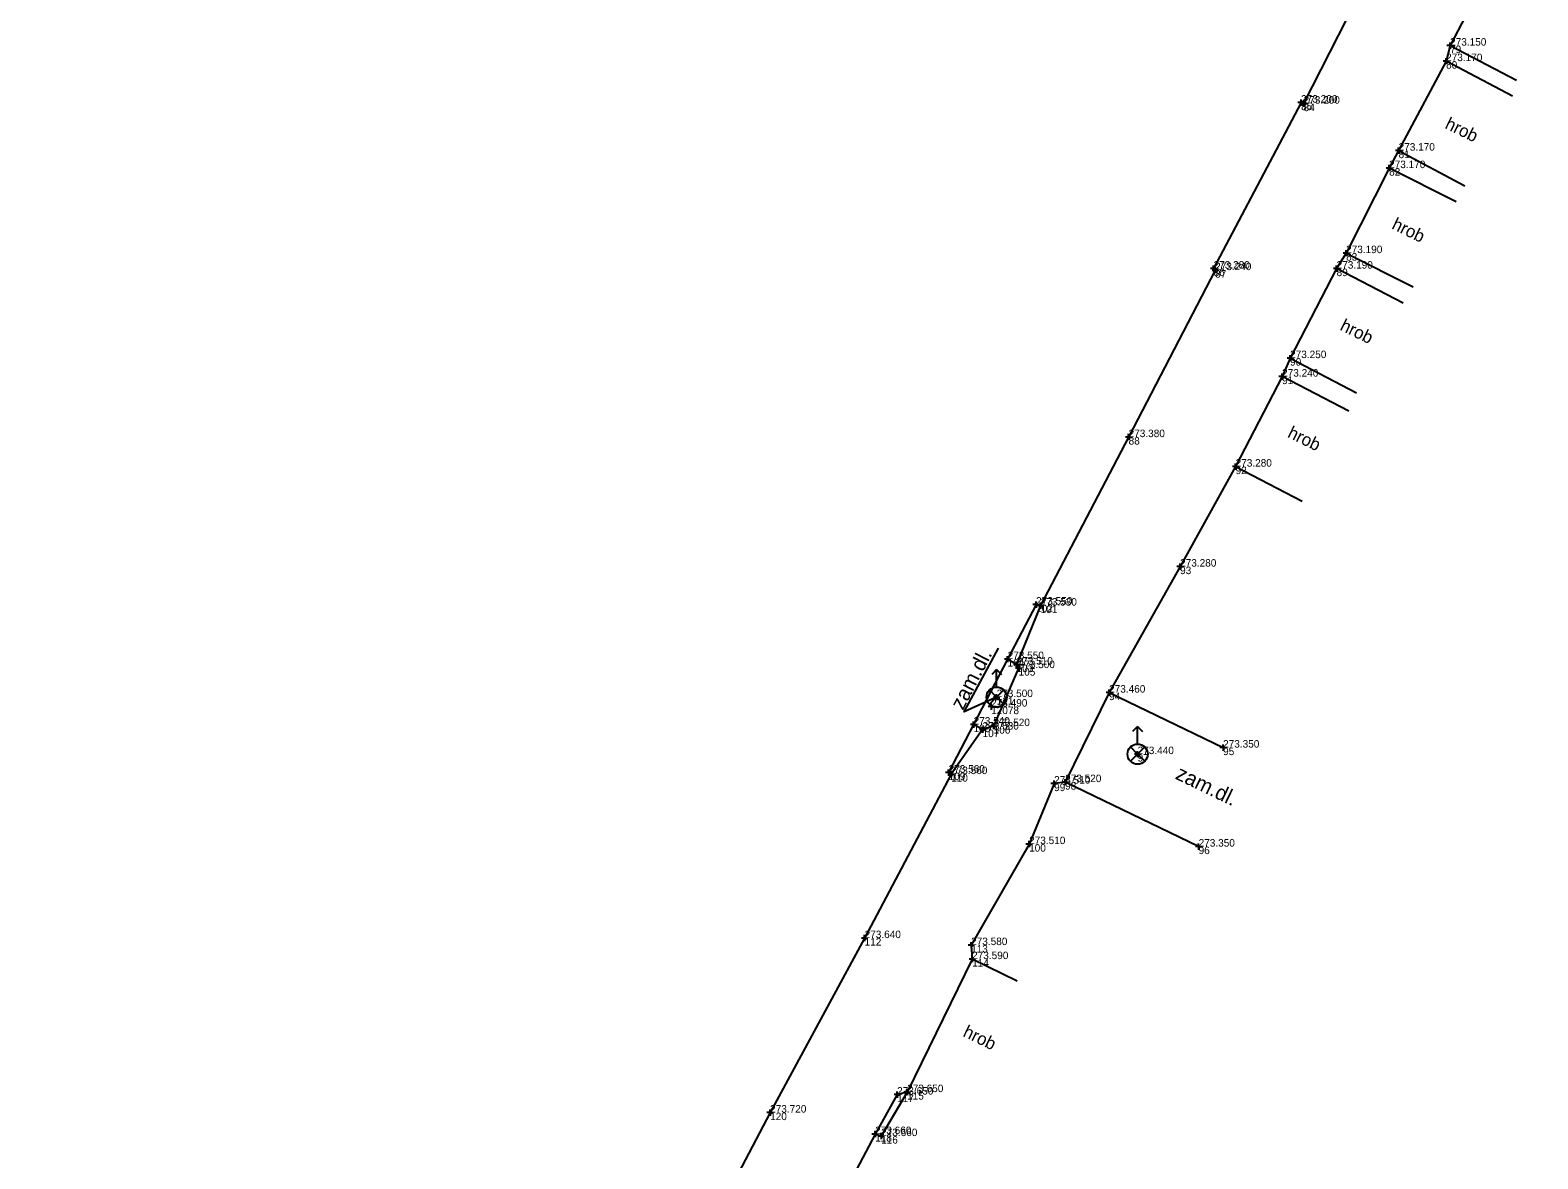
# Model space of a CAD drawing. Extents: x -776606 to -776076, y -974328 to -973875.
# Drawn here: x -776402.93 to -776372.78, y -974156.28 to -974133.71 of the extents above; entities that cross this region are included whole.
import ezdxf

# ---------------------------------------------------------------- set-up
doc = ezdxf.new("R2010")
doc.units = 0
for name, color, linetype in [('Body polohopisu', 7, 'Continuous'), ('Doplňkové značky', 7, 'Continuous'), ('Doplňující texty', 7, 'Continuous'), ('Rozhraní ploch', 7, 'Continuous'), ('Výšky bodů', 7, 'Continuous'), ('Čísla bodů', 7, 'Continuous')]:
    doc.layers.add(name, color=color, linetype=linetype)

msp = doc.modelspace()

# ---------------------------------------------------------------- linework, layer by layer
at = {"layer": 'Body polohopisu'}
for p, q in [((-776374.53, -974134.02), (-776374.593, -974134.02)), ((-776374.53, -974134.02), (-776374.53, -974133.958)), ((-776374.53, -974134.02), (-776374.468, -974134.02)), ((-776374.53, -974134.02), (-776374.53, -974134.083)), ((-776374.61, -974134.33), (-776374.672, -974134.33)), ((-776374.61, -974134.33), (-776374.61, -974134.268)), ((-776374.61, -974134.33), (-776374.547, -974134.33)), ((-776374.61, -974134.33), (-776374.61, -974134.393)), ((-776377.51, -974135.16), (-776377.573, -974135.16)), ((-776377.46, -974135.18), (-776377.522, -974135.18)), ((-776377.51, -974135.16), (-776377.51, -974135.098)), ((-776377.51, -974135.16), (-776377.448, -974135.16)), ((-776377.51, -974135.16), (-776377.51, -974135.223)), ((-776377.46, -974135.18), (-776377.46, -974135.118)), ((-776377.46, -974135.18), (-776377.397, -974135.18)), ((-776377.46, -974135.18), (-776377.46, -974135.243)), ((-776375.56, -974136.12), (-776375.623, -974136.12)), ((-776375.56, -974136.12), (-776375.56, -974136.057)), ((-776375.56, -974136.12), (-776375.498, -974136.12)), ((-776375.56, -974136.12), (-776375.56, -974136.182)), ((-776375.75, -974136.47), (-776375.812, -974136.47)), ((-776375.75, -974136.47), (-776375.75, -974136.407)), ((-776375.75, -974136.47), (-776375.688, -974136.47)), ((-776375.75, -974136.47), (-776375.75, -974136.532)), ((-776376.61, -974138.17), (-776376.672, -974138.17)), ((-776376.61, -974138.17), (-776376.61, -974138.108)), ((-776376.61, -974138.17), (-776376.547, -974138.17)), ((-776376.61, -974138.17), (-776376.61, -974138.233)), ((-776379.26, -974138.48), (-776379.323, -974138.48)), ((-776379.23, -974138.51), (-776379.292, -974138.51)), ((-776379.26, -974138.48), (-776379.26, -974138.417)), ((-776379.26, -974138.48), (-776379.198, -974138.48)), ((-776379.26, -974138.48), (-776379.26, -974138.542)), ((-776379.23, -974138.51), (-776379.23, -974138.448)), ((-776379.23, -974138.51), (-776379.167, -974138.51)), ((-776379.23, -974138.51), (-776379.23, -974138.573)), ((-776376.8, -974138.48), (-776376.863, -974138.48)), ((-776376.8, -974138.48), (-776376.8, -974138.417)), ((-776376.8, -974138.48), (-776376.738, -974138.48)), ((-776376.8, -974138.48), (-776376.8, -974138.542)), ((-776377.73, -974140.27), (-776377.792, -974140.27)), ((-776377.73, -974140.27), (-776377.73, -974140.208)), ((-776377.73, -974140.27), (-776377.667, -974140.27)), ((-776377.73, -974140.27), (-776377.73, -974140.333)), ((-776377.89, -974140.64), (-776377.953, -974140.64)), ((-776377.89, -974140.64), (-776377.89, -974140.578)), ((-776377.89, -974140.64), (-776377.828, -974140.64)), ((-776377.89, -974140.64), (-776377.89, -974140.703)), ((-776380.96, -974141.85), (-776381.022, -974141.85)), ((-776380.96, -974141.85), (-776380.96, -974141.787)), ((-776380.96, -974141.85), (-776380.897, -974141.85)), ((-776380.96, -974141.85), (-776380.96, -974141.912)), ((-776378.82, -974142.44), (-776378.883, -974142.44)), ((-776378.82, -974142.44), (-776378.82, -974142.378)), ((-776378.82, -974142.44), (-776378.758, -974142.44)), ((-776378.82, -974142.44), (-776378.82, -974142.503)), ((-776379.93, -974144.44), (-776379.93, -974144.378)), ((-776379.93, -974144.44), (-776379.993, -974144.44)), ((-776379.93, -974144.44), (-776379.868, -974144.44)), ((-776379.93, -974144.44), (-776379.93, -974144.503)), ((-776382.81, -974145.2), (-776382.873, -974145.2)), ((-776382.81, -974145.2), (-776382.81, -974145.138)), ((-776382.81, -974145.2), (-776382.748, -974145.2)), ((-776382.81, -974145.2), (-776382.81, -974145.263)), ((-776382.72, -974145.22), (-776382.782, -974145.22)), ((-776382.72, -974145.22), (-776382.72, -974145.157)), ((-776382.72, -974145.22), (-776382.657, -974145.22)), ((-776382.72, -974145.22), (-776382.72, -974145.282)), ((-776383.38, -974146.29), (-776383.443, -974146.29)), ((-776383.38, -974146.29), (-776383.38, -974146.228)), ((-776383.38, -974146.29), (-776383.318, -974146.29)), ((-776383.38, -974146.29), (-776383.38, -974146.353)), ((-776383.2, -974146.4), (-776383.263, -974146.4)), ((-776383.16, -974146.47), (-776383.223, -974146.47)), ((-776383.2, -974146.4), (-776383.2, -974146.338)), ((-776383.2, -974146.4), (-776383.138, -974146.4)), ((-776383.2, -974146.4), (-776383.2, -974146.463)), ((-776383.16, -974146.47), (-776383.16, -974146.407)), ((-776383.16, -974146.47), (-776383.098, -974146.47)), ((-776383.16, -974146.47), (-776383.16, -974146.532)), ((-776383.6, -974147.05), (-776383.662, -974147.05)), ((-776383.6, -974147.05), (-776383.6, -974146.988)), ((-776383.6, -974147.05), (-776383.537, -974147.05)), ((-776383.6, -974147.05), (-776383.6, -974147.113)), ((-776381.35, -974146.96), (-776381.412, -974146.96)), ((-776381.35, -974146.96), (-776381.35, -974146.897)), ((-776381.35, -974146.96), (-776381.287, -974146.96)), ((-776381.35, -974146.96), (-776381.35, -974147.022)), ((-776383.71, -974147.24), (-776383.772, -974147.24)), ((-776383.71, -974147.24), (-776383.71, -974147.177)), ((-776383.71, -974147.24), (-776383.647, -974147.24)), ((-776383.71, -974147.24), (-776383.71, -974147.302)), ((-776384.06, -974147.6), (-776384.123, -974147.6)), ((-776384.06, -974147.6), (-776384.06, -974147.537)), ((-776384.06, -974147.6), (-776383.998, -974147.6)), ((-776384.06, -974147.6), (-776384.06, -974147.662)), ((-776383.88, -974147.7), (-776383.943, -974147.7)), ((-776383.88, -974147.7), (-776383.88, -974147.638)), ((-776383.88, -974147.7), (-776383.818, -974147.7)), ((-776383.88, -974147.7), (-776383.88, -974147.763)), ((-776383.66, -974147.63), (-776383.723, -974147.63)), ((-776383.66, -974147.63), (-776383.66, -974147.568)), ((-776383.66, -974147.63), (-776383.598, -974147.63)), ((-776383.66, -974147.63), (-776383.66, -974147.693)), ((-776379.07, -974148.06), (-776379.07, -974147.998)), ((-776380.78, -974148.19), (-776380.843, -974148.19)), ((-776380.78, -974148.19), (-776380.78, -974148.128)), ((-776380.78, -974148.19), (-776380.718, -974148.19)), ((-776380.78, -974148.19), (-776380.78, -974148.253)), ((-776379.07, -974148.06), (-776379.133, -974148.06)), ((-776379.07, -974148.06), (-776379.008, -974148.06)), ((-776379.07, -974148.06), (-776379.07, -974148.123)), ((-776384.56, -974148.56), (-776384.623, -974148.56)), ((-776384.51, -974148.59), (-776384.573, -974148.59)), ((-776384.56, -974148.56), (-776384.56, -974148.498)), ((-776384.56, -974148.56), (-776384.498, -974148.56)), ((-776384.56, -974148.56), (-776384.56, -974148.623)), ((-776384.51, -974148.59), (-776384.51, -974148.527)), ((-776384.51, -974148.59), (-776384.448, -974148.59)), ((-776384.51, -974148.59), (-776384.51, -974148.652)), ((-776382.45, -974148.78), (-776382.513, -974148.78)), ((-776382.45, -974148.78), (-776382.45, -974148.718)), ((-776382.45, -974148.78), (-776382.388, -974148.78)), ((-776382.45, -974148.78), (-776382.45, -974148.843)), ((-776382.23, -974148.75), (-776382.292, -974148.75)), ((-776382.23, -974148.75), (-776382.23, -974148.688)), ((-776382.23, -974148.75), (-776382.167, -974148.75)), ((-776382.23, -974148.75), (-776382.23, -974148.812)), ((-776382.95, -974149.99), (-776383.013, -974149.99)), ((-776382.95, -974149.99), (-776382.95, -974149.927)), ((-776382.95, -974149.99), (-776382.888, -974149.99)), ((-776382.95, -974149.99), (-776382.95, -974150.052)), ((-776379.56, -974150.04), (-776379.623, -974150.04)), ((-776379.56, -974150.04), (-776379.56, -974149.978)), ((-776379.56, -974150.04), (-776379.498, -974150.04)), ((-776379.56, -974150.04), (-776379.56, -974150.103)), ((-776386.24, -974151.87), (-776386.302, -974151.87)), ((-776386.24, -974151.87), (-776386.24, -974151.807)), ((-776386.24, -974151.87), (-776386.177, -974151.87)), ((-776386.24, -974151.87), (-776386.24, -974151.932)), ((-776384.11, -974152.01), (-776384.172, -974152.01)), ((-776384.11, -974152.01), (-776384.11, -974151.948)), ((-776384.11, -974152.01), (-776384.047, -974152.01)), ((-776384.11, -974152.01), (-776384.11, -974152.073)), ((-776384.09, -974152.29), (-776384.09, -974152.228)), ((-776384.09, -974152.29), (-776384.152, -974152.29)), ((-776384.09, -974152.29), (-776384.027, -974152.29)), ((-776384.09, -974152.29), (-776384.09, -974152.353)), ((-776385.59, -974155), (-776385.59, -974154.938)), ((-776385.39, -974154.95), (-776385.453, -974154.95)), ((-776385.39, -974154.95), (-776385.39, -974154.888)), ((-776385.39, -974154.95), (-776385.328, -974154.95)), ((-776385.39, -974154.95), (-776385.39, -974155.013)), ((-776385.59, -974155), (-776385.652, -974155)), ((-776385.59, -974155), (-776385.527, -974155)), ((-776385.59, -974155), (-776385.59, -974155.062)), ((-776388.13, -974155.36), (-776388.193, -974155.36)), ((-776388.13, -974155.36), (-776388.13, -974155.297)), ((-776388.13, -974155.36), (-776388.068, -974155.36)), ((-776388.13, -974155.36), (-776388.13, -974155.422)), ((-776386.03, -974155.79), (-776386.093, -974155.79)), ((-776386.03, -974155.79), (-776386.03, -974155.728)), ((-776386.03, -974155.79), (-776385.968, -974155.79)), ((-776386.03, -974155.79), (-776386.03, -974155.853)), ((-776385.91, -974155.83), (-776385.973, -974155.83)), ((-776385.91, -974155.83), (-776385.91, -974155.768)), ((-776385.91, -974155.83), (-776385.848, -974155.83)), ((-776385.91, -974155.83), (-776385.91, -974155.893))]:
    msp.add_line(p, q, dxfattribs=at)
at = {"layer": 'Doplňkové značky'}
for p, q in [((-776383.6, -974146.5), (-776383.699, -974146.6)), ((-776383.6, -974146.848), (-776383.6, -974146.5)), ((-776383.6, -974146.5), (-776383.5, -974146.6)), ((-776383.6, -974147.05), (-776383.742, -974146.907)), ((-776383.6, -974147.05), (-776383.742, -974147.192)), ((-776383.6, -974147.05), (-776383.458, -974146.907)), ((-776383.6, -974147.05), (-776383.6, -974147.05)), ((-776383.6, -974147.05), (-776383.458, -974147.192)), ((-776380.78, -974147.64), (-776380.88, -974147.74)), ((-776380.78, -974147.988), (-776380.78, -974147.64)), ((-776380.78, -974147.64), (-776380.68, -974147.74)), ((-776380.78, -974148.19), (-776380.922, -974148.047)), ((-776380.78, -974148.19), (-776380.922, -974148.332)), ((-776380.78, -974148.19), (-776380.638, -974148.047)), ((-776380.78, -974148.19), (-776380.78, -974148.19)), ((-776380.78, -974148.19), (-776380.638, -974148.332))]:
    msp.add_line(p, q, dxfattribs=at)
for centre in [(-776383.6, -974147.05), (-776380.78, -974148.19)]:
    msp.add_circle(centre, 0.202, dxfattribs=at)
at = {"layer": 'Doplňující texty'}
msp.add_lwpolyline([(-776383.6, -974147.05), (-776384.249, -974147.344), (-776383.564, -974146.07)], dxfattribs=at)
at = {"layer": 'Rozhraní ploch'}
msp.add_line((-776376.61, -974138.17), (-776376.8, -974138.48), dxfattribs=at)
for points in [[(-776371.123, -974130.75), (-776372.45, -974130.05), (-776373.59, -974132.21), (-776374.53, -974134.02), (-776373.199, -974134.711)], [(-776375.72, -974131.76), (-776377.46, -974135.18), (-776377.51, -974135.16), (-776379.26, -974138.48), (-776379.23, -974138.51), (-776380.96, -974141.85), (-776382.72, -974145.22), (-776382.81, -974145.2), (-776383.38, -974146.29), (-776384.06, -974147.6), (-776384.56, -974148.56), (-776384.51, -974148.59), (-776386.24, -974151.87)], [(-776374.53, -974134.02), (-776374.61, -974134.33)], [(-776373.285, -974135.033), (-776374.61, -974134.33), (-776375.56, -974136.12), (-776374.235, -974136.823)], [(-776375.56, -974136.12), (-776375.75, -974136.47)], [(-776374.412, -974137.147), (-776375.75, -974136.47), (-776376.61, -974138.17), (-776375.272, -974138.847)], [(-776375.469, -974139.172), (-776376.8, -974138.48), (-776377.73, -974140.27), (-776376.399, -974140.962)], [(-776377.73, -974140.27), (-776377.89, -974140.64)], [(-776376.557, -974141.329), (-776377.89, -974140.64), (-776378.82, -974142.44), (-776377.487, -974143.129)], [(-776378.82, -974142.44), (-776379.93, -974144.44), (-776381.35, -974146.96), (-776382.23, -974148.75), (-776382.45, -974148.78), (-776382.95, -974149.99), (-776384.11, -974152.01), (-776384.09, -974152.29)], [(-776382.72, -974145.22), (-776383.2, -974146.4), (-776383.16, -974146.47), (-776383.66, -974147.63), (-776383.88, -974147.7), (-776384.51, -974148.59)], [(-776383.2, -974146.4), (-776383.38, -974146.29)], [(-776381.35, -974146.96), (-776379.07, -974148.06)], [(-776383.88, -974147.7), (-776384.06, -974147.6)], [(-776379.56, -974150.04), (-776382.23, -974148.75)], [(-776386.24, -974151.87), (-776388.13, -974155.36)], [(-776383.192, -974152.729), (-776384.09, -974152.29), (-776385.39, -974154.95), (-776385.91, -974155.83), (-776386.03, -974155.79), (-776386.53, -974156.74), (-776385.645, -974157.206)], [(-776385.39, -974154.95), (-776385.59, -974155), (-776386.03, -974155.79)], [(-776388.13, -974155.36), (-776389.83, -974158.6), (-776389.78, -974158.63), (-776391.56, -974162.08), (-776393.29, -974165.49), (-776395.18, -974169.05), (-776395.13, -974169.08), (-776396.81, -974172.12), (-776400.36, -974179.01), (-776402.93, -974177.7), (-776402.9, -974177.61)]]:
    msp.add_lwpolyline(points, dxfattribs=at)

# ---------------------------------------------------------------- texts
at = {"layer": 'Doplňující texty'}
for s, height, rotation, p in [('hrob', 0.25, 333.9465, (-776374.651, -974135.665)), ('hrob', 0.25, 333.9465, (-776375.715, -974137.674)), ('hrob', 0.25, 333.9465, (-776376.749, -974139.699)), ('hrob', 0.25, 333.9465, (-776377.799, -974141.843)), ('zam.dl.', 0.3, 62.5669, (-776384.275, -974147.329)), ('zam.dl.', 0.3, 334.2127, (-776380.045, -974148.675)), ('hrob', 0.25, 333.9465, (-776384.291, -974153.825))]:
    msp.add_text(s, height=height, rotation=rotation, dxfattribs=at).set_placement(p)
at = {"layer": 'Výšky bodů'}
for s, p in [('273.150', (-776374.53, -974134.02)), ('273.170', (-776374.61, -974134.33)), ('273.200', (-776377.51, -974135.16)), ('273.200', (-776377.46, -974135.18)), ('273.170', (-776375.56, -974136.12)), ('273.170', (-776375.75, -974136.47)), ('273.190', (-776376.61, -974138.17)), ('273.280', (-776379.26, -974138.48)), ('273.240', (-776379.23, -974138.51)), ('273.190', (-776376.8, -974138.48)), ('273.250', (-776377.73, -974140.27)), ('273.240', (-776377.89, -974140.64)), ('273.380', (-776380.96, -974141.85)), ('273.280', (-776378.82, -974142.44)), ('273.280', (-776379.93, -974144.44)), ('273.550', (-776382.81, -974145.2)), ('273.530', (-776382.72, -974145.22)), ('273.550', (-776383.38, -974146.29)), ('273.510', (-776383.2, -974146.4)), ('273.500', (-776383.16, -974146.47)), ('273.460', (-776381.35, -974146.96)), ('273.490', (-776383.71, -974147.24)), ('273.500', (-776383.6, -974147.05)), ('273.540', (-776384.06, -974147.6)), ('273.530', (-776383.88, -974147.7)), ('273.520', (-776383.66, -974147.63)), ('273.350', (-776379.07, -974148.06)), ('273.440', (-776380.78, -974148.19)), ('273.560', (-776384.56, -974148.56)), ('273.560', (-776384.51, -974148.59)), ('273.520', (-776382.23, -974148.75)), ('273.510', (-776382.45, -974148.78)), ('273.510', (-776382.95, -974149.99)), ('273.350', (-776379.56, -974150.04)), ('273.640', (-776386.24, -974151.87)), ('273.580', (-776384.11, -974152.01)), ('273.590', (-776384.09, -974152.29)), ('273.650', (-776385.59, -974155)), ('273.650', (-776385.39, -974154.95)), ('273.720', (-776388.13, -974155.36)), ('273.660', (-776386.03, -974155.79)), ('273.660', (-776385.91, -974155.83))]:
    msp.add_text(s, height=0.15, dxfattribs=at).set_placement(p)
at = {"layer": 'Čísla bodů'}
for s, p in [('79', (-776374.53, -974134.17)), ('80', (-776374.61, -974134.48)), ('85', (-776377.51, -974135.31)), ('84', (-776377.46, -974135.33)), ('81', (-776375.56, -974136.27)), ('82', (-776375.75, -974136.62)), ('83', (-776376.61, -974138.32)), ('86', (-776379.26, -974138.63)), ('87', (-776379.23, -974138.66)), ('89', (-776376.8, -974138.63)), ('90', (-776377.73, -974140.42)), ('91', (-776377.89, -974140.79)), ('88', (-776380.96, -974142)), ('92', (-776378.82, -974142.59)), ('93', (-776379.93, -974144.59)), ('102', (-776382.81, -974145.35)), ('101', (-776382.72, -974145.37)), ('104', (-776383.38, -974146.44)), ('103', (-776383.2, -974146.55)), ('105', (-776383.16, -974146.62)), ('111', (-776383.6, -974147.2)), ('94', (-776381.35, -974147.11)), ('12078', (-776383.71, -974147.39)), ('108', (-776384.06, -974147.75)), ('107', (-776383.88, -974147.85)), ('106', (-776383.66, -974147.78)), ('97', (-776380.78, -974148.34)), ('95', (-776379.07, -974148.21)), ('109', (-776384.56, -974148.71)), ('110', (-776384.51, -974148.74)), ('99', (-776382.45, -974148.93)), ('98', (-776382.23, -974148.9)), ('100', (-776382.95, -974150.14)), ('96', (-776379.56, -974150.19)), ('112', (-776386.24, -974152.02)), ('113', (-776384.11, -974152.16)), ('114', (-776384.09, -974152.44)), ('115', (-776385.39, -974155.1)), ('117', (-776385.59, -974155.15)), ('120', (-776388.13, -974155.51)), ('118', (-776386.03, -974155.94)), ('116', (-776385.91, -974155.98))]:
    msp.add_text(s, height=0.15, dxfattribs=at).set_placement(p)

doc.saveas('drawing.dxf')
